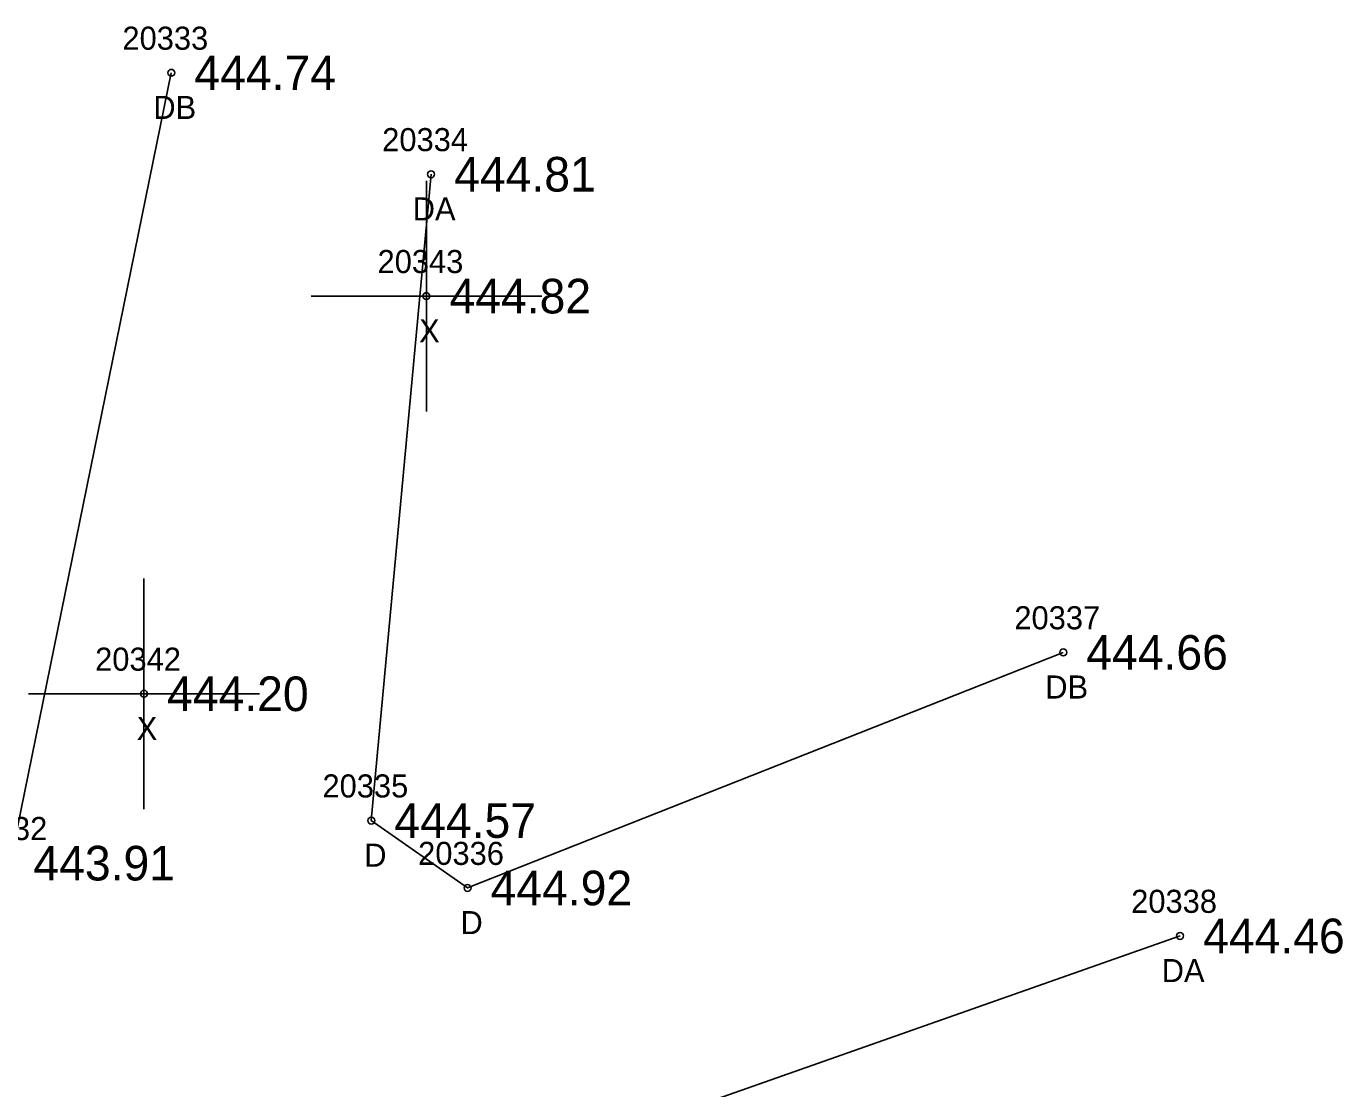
# Model space of a CAD drawing. Extents: x 1613836 to 1615109, y 777151 to 778248.
# Drawn here: x 1614922.8 to 1614979.9, y 777339.3 to 777385.3 of the extents above; entities that cross this region are included whole.
import ezdxf

# ---------------------------------------------------------------- set-up
doc = ezdxf.new("R2010")
doc.units = 0
for name, color, linetype in [('RD_EX_Driveway', 7, 'Continuous'), ('RD_EX_Driveway_txCode', 7, 'Continuous'), ('RD_EX_Misc', 7, 'Continuous'), ('RD_EX_Misc_txCode', 7, 'Continuous'), ('RD_EX_TX_Driveway_ELEV', 7, 'Continuous'), ('RD_EX_TX_Misc_ELEV', 7, 'Continuous'), ('RD_SMD_Locator', 7, 'Continuous')]:
    doc.layers.add(name, color=color, linetype=linetype)

msp = doc.modelspace()

# ---------------------------------------------------------------- linework, layer by layer
at = {"layer": 'RD_EX_Driveway'}
for points in [[(1614915.189, 777340.175), (1614922.151, 777349.063), (1614929.126, 777383.314)], [(1614940.384, 777378.918), (1614937.794, 777350.909), (1614941.963, 777347.987), (1614967.775, 777358.197)], [(1614972.837, 777345.909), (1614942.483, 777335.218), (1614934.979, 777324.495)]]:
    msp.add_lwpolyline(points, dxfattribs=at)
at = {"layer": 'RD_EX_Misc'}
for p, q in [((1614940.181, 777368.636), (1614940.181, 777378.636)), ((1614935.181, 777373.636), (1614945.181, 777373.636)), ((1614927.943, 777351.403), (1614927.943, 777361.403)), ((1614922.943, 777356.403), (1614932.943, 777356.403))]:
    msp.add_line(p, q, dxfattribs=at)
at = {"layer": 'RD_SMD_Locator'}
for centre in [(1614929.126, 777383.314), (1614940.384, 777378.918), (1614940.181, 777373.636), (1614967.775, 777358.197), (1614927.943, 777356.403), (1614937.794, 777350.909), (1614941.963, 777347.987), (1614972.837, 777345.909)]:
    msp.add_circle(centre, 0.15, dxfattribs=at)

# ---------------------------------------------------------------- texts
at = {"layer": 'RD_EX_Driveway_txCode'}
for s, p in [('20333', (1614927.008, 777384.314)), ('DB', (1614928.347, 777381.314)), ('20334', (1614938.265, 777379.918)), ('DA', (1614939.588, 777376.918)), ('20337', (1614965.657, 777359.197)), ('DB', (1614966.996, 777356.197)), ('20335', (1614935.676, 777351.909)), ('20332', (1614920.033, 777350.063)), ('D', (1614937.487, 777348.909)), ('20336', (1614939.822, 777348.987)), ('20338', (1614970.719, 777346.909)), ('D', (1614941.656, 777345.987)), ('DA', (1614972.042, 777343.909))]:
    msp.add_text(s, height=1, dxfattribs=at).set_placement(p)
at = {"layer": 'RD_EX_Misc_txCode'}
for s, p in [('20343', (1614938.063, 777374.636)), ('X', (1614939.866, 777371.636)), ('20342', (1614925.825, 777357.403)), ('X', (1614927.628, 777354.403))]:
    msp.add_text(s, height=1, dxfattribs=at).set_placement(p)
at = {"layer": 'RD_EX_TX_Driveway_ELEV'}
for s, p in [('444.74', (1614930.126, 777382.564)), ('444.81', (1614941.384, 777378.168)), ('444.66', (1614968.775, 777357.447)), ('444.57', (1614938.794, 777350.159)), ('443.91', (1614923.151, 777348.313)), ('444.92', (1614942.963, 777347.237)), ('444.46', (1614973.837, 777345.159))]:
    msp.add_text(s, height=1.5, dxfattribs=at).set_placement(p)
at = {"layer": 'RD_EX_TX_Misc_ELEV'}
for s, p in [('444.82', (1614941.181, 777372.886)), ('444.20', (1614928.943, 777355.653))]:
    msp.add_text(s, height=1.5, dxfattribs=at).set_placement(p)

doc.saveas('drawing.dxf')
